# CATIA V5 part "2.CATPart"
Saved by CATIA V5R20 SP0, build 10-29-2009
Part number: Part1
Material "Aluminium": density 2710 kg/m3, Young's modulus 7e+10 Pa, Poisson ratio 0.346, thermal expansion 2.36e-05 1/K
Bounding box of the stored display mesh (mm): x -162.337 to 102.6, y -42.6 to 42.6, z -23.2 to 40
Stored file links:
  E:\Ehsan\Amoozesh\CATIA\CATIA Course\Advanced\Videos\Session-14\2.CATPart
  D:\CATIA V5R20\B20\intel_a\startup\materials\Catalog.CATMaterial
  D:\CATIA V5R20\B20\intel_a\resources\graphic\figures\CATIA_EnvironmentMap_Potsdamer_512x512.jpg
  D:\CATIA V5R20\B20\intel_a\resources\graphic\figures\CATIA_EnvironmentMap_DSYellow_512x512.jpg
  D:\CATIA V5R20\B20\intel_a\resources\graphic\figures\CATIA_EnvironmentMap_DSRed_512x512.jpg
  D:\CATIA V5R20\B20\intel_a\resources\graphic\figures\CATIA_EnvironmentMap_DSBrown_512x512.jpg
  D:\CATIA V5R20\B20\intel_a\resources\graphic\figures\CATIA_EnvironmentMap_Soft_512x512.jpg
  D:\CATIA V5R20\B20\intel_a\resources\graphic\figures\CATIA_EnvironmentMap_Satin_512x512.jpg
  D:\CATIA V5R20\B20\intel_a\resources\graphic\figures\CATIA_EnvironmentMap_YellowSatin_512x512.jpg
  D:\CATIA V5R20\B20\intel_a\resources\graphic\figures\CATIA_EnvironmentMap_Garden_512x512.jpg
  D:\CATIA V5R20\B20\intel_a\resources\graphic\figures\CATIA_EnvironmentMap_DSBlack_512x512.jpg
  D:\CATIA V5R20\B20\intel_a\resources\graphic\figures\CATIA_EnvironmentMap_Default_512x512.jpg
  D:\CATIA V5R20\B20\intel_a\resources\graphic\figures\CATIA_EnvironmentMap_DSGreen_512x512.jpg
  D:\CATIA V5R20\B20\intel_a\resources\graphic\figures\CATIA_EnvironmentMap_Grey_512x512.jpg
  D:\CATIA V5R20\B20\intel_a\resources\graphic\figures\CATIA_EnvironmentMap_NonLinear_512x512.jpg
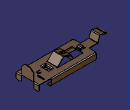
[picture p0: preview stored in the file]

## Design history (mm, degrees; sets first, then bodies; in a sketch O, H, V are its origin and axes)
SheetMetalParameters1: Thickness 1.6, BendRadius 1, KFactor 0.274228 {= log(min(100,max(20*SheetMetalParameters1.BendRadius,SheetMetalParameters1.Thickness)/SheetMetalParameters1.Thickness))/log(100)/2}, ReliefRadialLength 1, ReliefAxialLength 2, MinimumBendRadius 0
Set1
  Plane1: type Offset, RefPlane yz-plane, Offset 60
Body1 (main body), material "Aluminium"
  Sketch1 on xy-plane, origin (0, 0, 0), H (1, 0, 0), V (0, 1, 0)
    line L1 (100, 40) -> (100, -40)
    line L2 (100, -40) -> (-100, -40)
    line L3 (-100, -40) -> (-100, -15)
    line L4 (-100, 40) -> (100, 40)
    point P5 (-100, 0)
    line L5 (-100, -15) -> (-130, -15)
    line L6 (-130, -15) -> (-130, 15)
    line L7 (-130, 15) -> (-100, 15)
    point P8 (-30, 0)
    line L8 (15, 20) -> (15, -20)
    line L9 (15, -20) -> (-75, -20)
    line L10 (-75, -20) -> (-75, 20)
    line L11 (-75, 20) -> (15, 20)
    construction line L12 (75, 30) -> (75, 10)
    point P14 (75, 10)
    line L13 (77.5, 30) -> (77.5, 10)
    line L14 (72.5, 10) -> (72.5, 30)
    arc A1 centre (75, 10) radius 2.5 from (77.5, 10) to (72.5, 10) cw
    arc A2 centre (75, 30) radius 2.5 from (72.5, 30) to (77.5, 30) cw
    point P15 (77.5, 30)
    point P16 (77.5, 10)
    point P17 (72.5, 10)
    point P18 (72.5, 30)
    point P19 (77.5, -10)
    point P20 (77.5, -30)
    line L15 (77.5, -30) -> (77.5, -10)
    point P21 (72.5, -30)
    point P22 (72.5, -10)
    line L16 (72.5, -10) -> (72.5, -30)
    point P23 (75, -10)
    arc A3 centre (75, -10) radius 2.5 from (77.5, -10) to (72.5, -10) ccw
    arc A4 centre (75, -30) radius 2.5 from (72.5, -30) to (77.5, -30) ccw
    construction line L17 (75, -30) -> (75, -10)
    line L18 (-100, 15) -> (-100, 40)
    distance L12 L13 = 2.5
    length L4 = 200
    length L1 = 80
    length L7 = 30
    length L11 = 90
    length L6 = 30
    distance L8 V = 15
    length L8 = 40
    length L14 = 20
    distance P14 P23 = 20
    distance L12 L1 = 25
    vertical: L1 V, L3 V, L6 V, L8 V, L10 V, L12 V, L18 V
    horizontal: L2 H, L4 H, L5 H, L7 H, L9 H, L11 H
    equidistance: L1 L3 O, L2 L4 O, L5 L7 P5, L8 L10 P8, L9 L11 P8
    coincidence: P8 H, L3 L18, P5 H
    tangency: A1 L13, A2 L13, A1 L14, A2 L14
    symmetry: P16 P19 H, P15 P20 H, L13 L15 H, P18 P21 H, P17 P22 H, L14 L16 H, A1 A3 H, A2 A4 H, L12 L17 H
  Wall1: Thickness 1.6, Profile Sketch1
  d_NewWallOnEdge1: NewWallOnEdge_Length 65, NewWallOnEdge_HeightLimitOffset 0, NewWallOnEdge_WidthOffset1 -2, NewWallOnEdge_WidthOffset2 -2, NewWallOnEdge_Angle 135, NewWallOnEdge_BendRadiusValue 1 {= SheetMetalParameters1.BendRadius}, NewWallOnEdge_BendTable SheetMetalParameters1, NewWallOnEdge_Edge edge [face of Wall1 | face of Wall1], NewWallOnEdge_GapValue 0, KFacteur 0.274228 {= log(min(100,max(20*d_NewWallOnEdge1.Radius,SheetMetalParameters1.Thickness)/SheetMetalParameters1.Thickness))/log(100)/2}
  Corner1: CornerRadius 18, CornerChamferEdges (edge [face of d_NewWallOnEdge1 | face of d_NewWallOnEdge1]; edge [face of d_NewWallOnEdge1 | face of d_NewWallOnEdge1])
  CutOut1: Direction Sketch8, EndLimit through (limit type 2), Orientation true, Profile Sketch8, StartLimit through (limit type 2)
  FlatBend1: FlatBendAngle 135, FlatBendAngle 120, Axis Sketch7, FixedPoint vertex [face of d_NewWallOnEdge1 | face of d_NewWallOnEdge1 | face of d_NewWallOnEdge1 | face of d_NewWallOnEdge1], FlatBendKFactor 0.274228 {= log(min(100,max(20*FlatBend1.FlatBendRadius,SheetMetalParameters1.Thickness)/SheetMetalParameters1.Thickness))/log(100)/2}, FlatBendKFactor 0.274228 {= log(min(100,max(20*FlatBend1.FlatBendRadius,SheetMetalParameters1.Thickness)/SheetMetalParameters1.Thickness))/log(100)/2}, FlatBendRadius 1 {= SheetMetalParameters1.BendRadius}, FlatBendRadius 1 {= SheetMetalParameters1.BendRadius}
  d_NewWallOnEdge2: NewWallOnEdge_Length 40, NewWallOnEdge_HeightLimitOffset 0, NewWallOnEdge_WidthOffset1 -20, NewWallOnEdge_WidthOffset2 -20, NewWallOnEdge_Angle 90, NewWallOnEdge_BendRadiusValue 1 {= d_NewWallOnEdge2.Clearance}, NewWallOnEdge_BendTable SheetMetalParameters1, NewWallOnEdge_Edge edge [face of Wall1 | face of Wall1], NewWallOnEdge_GapValue 0, KFacteur 0.274228 {= log(min(100,max(20*d_NewWallOnEdge2.Radius,SheetMetalParameters1.Thickness)/SheetMetalParameters1.Thickness))/log(100)/2}
  Chamfer1: ChamferAngle 45, ChamferLength1 10, ChamferLength2 0.8, ChamferPropagation 1, ChamferReverse false, ChamferType 1, CornerChamferEdges (edge [face of d_NewWallOnEdge2 | face of d_NewWallOnEdge2]; edge [face of d_NewWallOnEdge2 | face of d_NewWallOnEdge2])
  d_NewWallOnEdge3: NewWallOnEdge_Length 20, NewWallOnEdge_HeightLimitOffset 0, NewWallOnEdge_WidthOffset1 0, NewWallOnEdge_WidthOffset2 0, NewWallOnEdge_Angle 90, NewWallOnEdge_BendRadiusValue 1 {= d_NewWallOnEdge3.Clearance}, NewWallOnEdge_BendTable SheetMetalParameters1, NewWallOnEdge_Edge (edge [face of Wall1 | face of Wall1]; edge [face of Wall1 | face of Wall1]), NewWallOnEdge_GapValue 0, KFacteur 0.274228 {= log(min(100,max(20*d_NewWallOnEdge3.Radius,SheetMetalParameters1.Thickness)/SheetMetalParameters1.Thickness))/log(100)/2}
  Corner2: CornerRadius 3, CornerChamferEdges (edge [face of d_NewWallOnEdge3 | face of d_NewWallOnEdge3]; edge [face of d_NewWallOnEdge3 | face of d_NewWallOnEdge3]; edge [face of d_NewWallOnEdge3 | face of d_NewWallOnEdge3]; edge [face of d_NewWallOnEdge3 | face of d_NewWallOnEdge3])
  d_NewWallOnEdge4: NewWallOnEdge_Length 20, NewWallOnEdge_HeightLimitOffset 0, NewWallOnEdge_WidthLimit2 Plane1, NewWallOnEdge_WidthOffset1 0, NewWallOnEdge_WidthOffset2 0, NewWallOnEdge_Angle 90, NewWallOnEdge_BendRadiusValue 1 {= d_NewWallOnEdge4.Clearance}, NewWallOnEdge_BendTable SheetMetalParameters1, NewWallOnEdge_Edge edge [face of Wall1 | face of Wall1], NewWallOnEdge_GapValue 0, KFacteur 0.274228 {= log(min(100,max(20*d_NewWallOnEdge4.Radius,SheetMetalParameters1.Thickness)/SheetMetalParameters1.Thickness))/log(100)/2}
  SHM_Mirror1: MirroringPlane zx-plane, ObjectToMirror d_NewWallOnEdge4
  d_NewWallOnEdge5: NewWallOnEdge_Length 20, NewWallOnEdge_HeightLimitOffset 0, NewWallOnEdge_WidthOffset1 0, NewWallOnEdge_WidthOffset2 0, NewWallOnEdge_Angle 90, NewWallOnEdge_BendRadiusValue 1 {= d_NewWallOnEdge5.Clearance}, NewWallOnEdge_BendTable SheetMetalParameters1, NewWallOnEdge_Edge (edge [face of SHM_Mirror1 | face of SHM_Mirror1]; edge [face of d_NewWallOnEdge4 | face of d_NewWallOnEdge4]), NewWallOnEdge_GapValue 0, KFacteur 0.274228 {= log(min(100,max(20*d_NewWallOnEdge5.Radius,SheetMetalParameters1.Thickness)/SheetMetalParameters1.Thickness))/log(100)/2}
  Flange1: Angle 90, Length 10, Radius 3.2, KFacteur 0.400515 {= log(min(100,max(20*Flange1.Radius,SheetMetalParameters1.Thickness)/SheetMetalParameters1.Thickness))/log(100)/2}, Guide edge [face of d_NewWallOnEdge4 | face of d_NewWallOnEdge4]
  Flange2: Angle 90, Length 10, Radius 3.2, KFacteur 0.400515 {= log(min(100,max(20*Flange2.Radius,SheetMetalParameters1.Thickness)/SheetMetalParameters1.Thickness))/log(100)/2}, Guide edge [face of SHM_Mirror1 | face of SHM_Mirror1]
  dMultiCornerRelief1
  Flange3: Angle 108, Length 20, Radius 1, KFacteur 0.274228 {= log(min(100,max(20*Flange3.Radius,SheetMetalParameters1.Thickness)/SheetMetalParameters1.Thickness))/log(100)/2}, Guide edge [face of Wall1 | face of Wall1]
  Flange4: Angle 90, Length 20, Radius 1, KFacteur 0.274228 {= log(min(100,max(20*Flange4.Radius,SheetMetalParameters1.Thickness)/SheetMetalParameters1.Thickness))/log(100)/2}, Guide edge [face of Flange3 | face of Flange3]
  Flange5: Angle 53.1301 {= 2*atan(Flange5.Radius/Flange5.Length)}, Length 2, Radius 1, KFacteur 0.274228 {= log(min(100,max(20*Flange5.Radius,SheetMetalParameters1.Thickness)/SheetMetalParameters1.Thickness))/log(100)/2}, Guide edge [face of Flange4 | face of Flange4]
  Sketch2 on face of Wall1, origin (51.0569, 0.9892, 1.6), H (1, 0, 0), V (0, 1, 0)
    point P1 (11.4431, -0.9892)
    reference projected line E1 (48.9431, 39.0108) -> (-151.0569, 39.0108) from edge [face of Wall1 | face of Wall1]
    reference projected line E2 (21.4431, -10.9892) -> (21.4431, -30.9892) from edge [face of Wall1 | face of Wall1]
    distance P1 E1 = 40
    distance P1 E2 = 10
  d_Stamp1: KFacteur 0.274228 {= SheetMetalParameters1.KFactor}, NewRoot_AttribNormalisation "No Standard", Stamp_FilletRadius 1, Stamp_IntersectFilletRadius 2
  Sketch3 on face of Wall1, origin (0, 0, 1.6), H (1, 0, 0), V (0, 1, 0)
    line L1 (25.5286, 12.5849) -> (42.4509, 12.5849)
    line L2 (42.4509, 12.5849) -> (42.4509, -13.3146)
    line L3 (42.4509, -13.3146) -> (25.5286, -13.3146)
    line L4 (25.5286, -13.3146) -> (25.5286, 12.5849)
    horizontal: L1 H, L3 H
    vertical: L2 V, L4 V
  d_Stamp2: NewRoot_AttribNormalisation "No Standard", Stamp_FilletRadius 1, Stamp_IntersectFilletRadius 2
  Sketch4 on face of d_Stamp2, origin (34.4479, 0, -6.4), H (1, 0, 0), V (0, 1, 0)
    point P1 (0, 0)
    reference projected point E1 (0, 0) from Sketch6.P1
    coincidence: E1 P1
  Hole1: placed by Sketch4, at (34.4479, 0, -6.4) direction (0, 0, -1), diameter 5, depth 10
  Sketch5 on face of Wall1, origin (-86.1074, -0.8902, 1.6), H (1, 0, 0), V (0, 1, 0)
    point P1 (0, 0)
  d_Stamp3: NewRoot_AttribNormalisation "No Standard", Stamp_FilletRadius 1, Stamp_IntersectFilletRadius 2
  Sketch6 on face of d_Stamp2, origin (0, 0, -6.4), H (1, 0, 0), V (0, 1, 0)
    point P1 (34.4479, 0)
    reference projected line E1 (41.7509, 10.9686) -> (41.7509, -11.6984) from edge [face of d_Stamp2 | face of d_Stamp2]
    reference projected line E2 (27.1449, -11.6984) -> (27.1449, 10.9686) from edge [face of d_Stamp2 | face of d_Stamp2]
    coincidence: P1 H
    equidistance: E1 E2 P1
  Sketch7 on face of d_NewWallOnEdge1, origin (8.3, 0, 8.3), H (0, 1, 0), V (-0.7071, 0, 0.7071)
    line L1 (-26.6298, 46.1075) -> (27.5176, 46.1075)
    line L2 (-24.9574, 21.4025) -> (28.0619, 21.4025)
    horizontal: L1 H, L2 H
  Sketch8 on face of d_NewWallOnEdge1, origin (0, 0, 1.6), H (1, 0, 0), V (0, 1, 0)
    construction line L1 (-56.9627, 0) -> (-26.9627, 0)
    point P1 (-56.9627, 0)
    line L2 (-56.9627, 6) -> (-26.9627, 6)
    line L3 (-26.9627, -6) -> (-56.9627, -6)
    arc A1 centre (-26.9627, 0) radius 6 from (-26.9627, 6) to (-26.9627, -6) cw
    arc A2 centre (-56.9627, 0) radius 6 from (-56.9627, -6) to (-56.9627, 6) cw
    reference projected arc E1 centre (-56.9627, 0) radius 18 from (-56.9627, 18) to (-74.9627, 0) ccw from edge [face of d_NewWallOnEdge1 | face of Corner1]
    distance L1 L2 = 6
    length L1 = 30
    coincidence: P1 H
    horizontal: L1 H
    tangency: A1 L2, A2 L2, A1 L3, A2 L3
    concentricity: P1 E1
